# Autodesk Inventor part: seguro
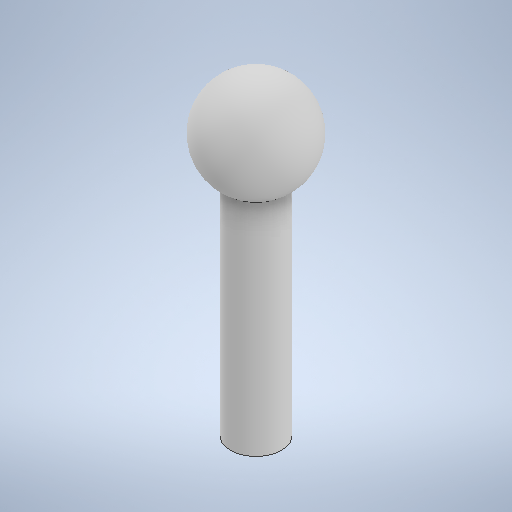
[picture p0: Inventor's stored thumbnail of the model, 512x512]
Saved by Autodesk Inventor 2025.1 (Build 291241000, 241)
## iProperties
Created: 2026-01
Part Number: seguro
Material: Genérico
Document SubType Name: Modeling
Designer: Usuario
Density: 1 g/cm^3
Appearance: Valor por defecto
Author: Usuario
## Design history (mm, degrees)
sketch "Boceto1"
  geometry: C1 r 1.95 at (0, 0); 1 further point
  constraints: 1 centre point, 1 coincident
  dimensions: "d0" = 3.9 diameter of C1
extrude "Extrusión1" new body sketch "Boceto1" distance "d1" = 20; taper "d2" = 0 deg
sketch "Boceto2"
  geometry: L1 (-3.75, 0)-(3.75, 0); C1 r 1.95 at (0, 0) reference; A1 r 3.75 centre (0, 0) between (-3.75, 0) and (3.75, 0); 2 further points
  constraints: 2 end point, 2 point on circle, 1 centre point, 1 coincident, 1 horizontal
  dimensions: "d3" = 7.5 diameter of A1
revolve "Revolución1" sketch "Boceto2" stored, may be unused: angle "d4" = 90 deg
node "Sólido1"
